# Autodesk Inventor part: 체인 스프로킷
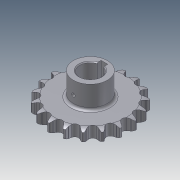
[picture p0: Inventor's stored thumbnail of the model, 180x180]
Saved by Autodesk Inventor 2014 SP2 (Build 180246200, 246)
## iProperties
Created: 2014-07
Part Number: 체인 스프로킷
Material: 강철
Document SubType Name: Modeling
Designer: KYOUNG IL JANG
Density: 1 g/cm^3
Appearance: 강철
CustomPartVersion: 1
Company: 한국ATC센터
Author: KYOUNG IL JANG
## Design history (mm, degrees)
sketch "이론적 톱니 프로파일"
  geometry: L1 (0, 0)-(0, 45.567); L2 (0, 0)-(14.795, 43.098); L3 (0, 45.567)-(14.795, 43.098); L4 (0, 45.567)-(5.661, 50.015); L5 (5.661, 50.015)-(-5.141, 45.406); L6 (-12.428, 43.493)-(-5.573, 46.417); L7 (-5.141, 45.406)-(-5.573, 46.417); L8 (5.573, 46.417)-(5.141, 45.406); L9 (0, 0)-(8.138, 48.771); A1 r 45.567 centre (0, 0) between (0, 45.567) and (14.795, 43.098); A2 r 49.445 centre (0, 0) between (7.302, 48.903) and (-7.302, 48.903); A3 r 4.545 centre (0, 45.567) between (-3.574, 42.758) and (3.574, 42.758); A4 r 7.453 centre (12.428, 43.493) between (7.302, 48.903) and (5.573, 46.417); A5 r 7.453 centre (-12.428, 43.493) between (-5.573, 46.417) and (-7.302, 48.903); A6 r 11.745 centre (5.661, 50.015) between (-5.141, 45.406) and (-3.574, 42.758); A7 r 11.745 centre (-5.661, 50.015) between (3.574, 42.758) and (5.141, 45.406); 2 further points
  constraints: 18 end point, 15 point on circle, 7 centre point, 3 coincident, 3 point on line, 3 symmetric about line, 3 tangent, 1 equal radius, 1 midpoint, 1 parallel, 1 vertical, 1 other
  dimensions: "d0" = 91.13301 diameter of A1 (computed from da_p, da_z); "d2" = 18.9474 deg angle of L2 L1 (computed from da_z); "d3" = 4.545 radius of A3 (= 0.5 x da_Dr + da_SC); "d10" = 128.158 deg angle of L4 L1 (computed from da_z); "d11" = 15.0526 deg angle of L5 L4 (computed from da_z); "d12" = 7.2 distance of L3.start L4.end (= 0.8 x da_Dr); "d13" = 11.745 distance of L4.end L5.end (= 1.3 x da_Dr + da_SC); "d14" = 12.6 distance of A4.centre L1.end (= 1.4 x da_Dr); "d23" = 4.5 distance from line of L9.end L3 (= da_Ha)
sketch "톱니 프로파일"
  geometry: L1 (0, 0)-(0, 45.567); L2 (0, 45.567)-(4.203, 43.837); L3 (0, 45.567)-(-4.203, 43.837); A1 r 4.545 centre (0, 45.567) between (-4.203, 43.837) and (4.203, 43.837); A2 r 22.68 centre (25.176, 35.206) between (7.12, 48.93) and (4.203, 43.837); A3 r 22.68 centre (-25.176, 35.206) between (-4.203, 43.837) and (-7.12, 48.93); A4 r 49.445 centre (0, 0) between (-7.12, 48.93) and (7.12, 48.93) reference; 1 further point
  constraints: 9 point on circle, 6 end point, 3 centre point, 2 tangent, 1 coincident, 1 equal radius, 1 vertical, 1 other
  dimensions: "d44" = 135.263 deg angle of L3 L2 (= da_Alfa); "d45" = 22.68 radius of A2 (= da_Re); "d46" = 4.545 radius of A1 (= da_Ri)
sketch "단면 프로파일"
  geometry: L1 (49.445, 0)-(-49.445, 0) reference; L2 (33.265, 6.65)-(-33.265, 6.65); L3 (-33.265, 6.65)-(-33.265, -6.65); L4 (-33.265, -6.65)-(33.265, -6.65); L5 (33.265, -6.65)-(33.265, 6.65); L6 (33.265, 6.65)-(49.445, 6.65); L7 (49.445, 6.65)-(49.445, -6.65); L8 (49.445, -6.65)-(33.265, -6.65); L9 (33.265, -6.65)-(33.265, 6.65); L10 (42.183, 6.65)-(0, 6.65); L11 (0, 6.65)-(0, -6.65); L12 (0, -6.65)-(42.183, -6.65); L13 (0, 6.65)-(0, -6.65); L14 (49.445, 4.775)-(49.445, -4.775); A1 r 15 centre (42.183, -8.35) between (49.445, 4.775) and (42.183, 6.65); A2 r 15 centre (42.183, 8.35) between (42.183, -6.65) and (49.445, -4.775); 2 further points
  constraints: 26 end point, 7 midpoint, 5 perpendicular, 4 parallel, 4 point on circle, 3 point on line, 3 symmetric about line, 2 centre point, 2 horizontal, 2 tangent, 1 collinear, 1 other
  dimensions: "d30" = 13.3 distance between parallel lines of L8 L6 (= da_Bf); "d31" = 66.53007 distance between parallel lines of L3 L5 (= da_Ds); "d32" = 13.3 distance between parallel lines of L4 L2 (= da_Bs); "d33" = 1.875 distance from line of L14.start L6 (= da_Ba); "d34" = 15 radius of A1 (= da_Rx); "d43" = 6.65 distance between parallel lines of L4 L1 (computed from da_k, da_pt, da_Bs)
revolve "슈라우드" stored, may be unused: angle "d36" = 90 deg
revolve "스트랜드" stored, may be unused: angle "d37" = 90 deg
extrude "이론적 톱니" cut sketch "이론적 톱니 프로파일" stored distance "d18" = 10; taper "d19" = 0 deg; dims "d49" = 0, "form_type" = 0 [user parameter]
extrude "톱니" cut sketch "톱니 프로파일" stored distance "d47" = 10; taper "d48" = 0 deg; dims "d50" = 10, "form_type" = 0 [user parameter]
node "타이밍 평면"
node "작업 평면3"
sketch "스케치5"
  geometry: C1 r 20 at (0, -45.567); 1 further point
  constraints: 1 centre point, 1 coincident
  dimensions: "d52" = 40 diameter of C1
extrude "돌출4" join sketch "스케치5" stored distance "d53" = 10; taper "d54" = 0 deg
sketch "스케치6"
  geometry: L1 (4, 11.843)-(4, 16.5); L2 (4, 16.5)-(-4, 16.5); L3 (-4, 16.5)-(-4, 11.843); A1 r 12.5 centre (0, 0) between (4, 11.843) and (-4, 11.843); 1 further point
  constraints: 6 end point, 2 parallel, 2 point on circle, 1 centre point, 1 coincident, 1 perpendicular, 1 vertical
  dimensions: "d55" = 25 diameter of A1; "d56" = 29 dimension on A1 L2 (computed from d55); "d57" = 8 distance of L1.end L2.end
extrude "돌출5" cut sketch "스케치6" stored distance "d58" = 10; taper "d59" = 0 deg
fillet "모깎기2" dims "d60" = 3
chamfer "모따기1" distance "d61" = 1; stored, may be unused: second distance "d62" = 2, angle "d63" = 45 deg
node "작업 평면4"
sketch "스케치7"
  geometry: L1 (-13.5, -13.3)-(13.5, -13.3) reference; 4 further points
  constraints: 1 vertical alignment
  dimensions: "d65" = 25 distance from line of point (0, 11.7) L1
hole "구멍1" sketch "스케치7" at (0, 11.7) diameter "d66" = 4.134; stored, may be unused: countersink angle "d70" = 90 deg, drill point angle "d72" = 118 deg; dims "d67" = 6, "d68" = 4, "d69" = 2, "d71" = 8
body "Solid1"
pattern_linear "스트랜드 패턴" dims "d40" = 24 (= da_pt)
pattern_circular "톱니 패턴" dims angle "d21" = 360 deg
other parameters: "da_p" = 15 [user parameter; used in 1 equation term], "da_Dr" = 9 [user parameter; used in 4 equation terms], "da_SC" = 0.045 [user parameter; used in 2 equation terms], "da_Ha" = 4.5 [user parameter; used in 1 equation term], "da_pt" = 24 [user parameter; used in 2 equation terms], "da_Bf" = 13.3 [user parameter; used in 1 equation term], "d28" = 0, "d29" = 0, "da_Ba" = 1.875 [user parameter; used in 1 equation term], "da_Rx" = 15 [user parameter; used in 1 equation term], "da_Ra" = 0.6 [user parameter], "da_Bs" = 13.3 [user parameter; used in 2 equation terms], "da_Ds" = 66.53007 [user parameter; used in 1 equation term], "d42" = 0, "da_Re" = 22.68 [user parameter; used in 1 equation term], "da_Ri" = 4.545 [user parameter; used in 1 equation term], "da_Alfa" = 135.263 deg [user parameter; used in 1 equation term]
